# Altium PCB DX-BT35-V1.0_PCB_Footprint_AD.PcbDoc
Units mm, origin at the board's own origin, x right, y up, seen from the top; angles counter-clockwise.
Board outline 152.4 x 101.6 mm, 2 copper layers (Top Layer, Bottom Layer); 1 components, 0 nets, 26 pads, 0 vias.
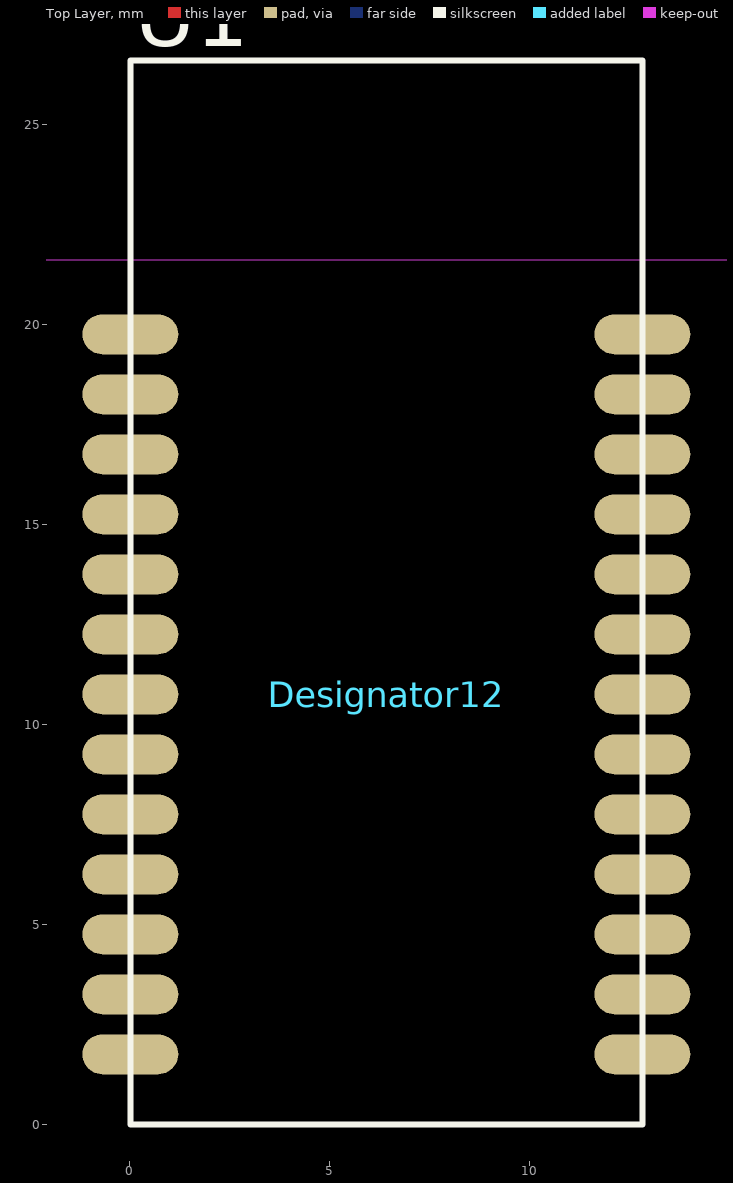
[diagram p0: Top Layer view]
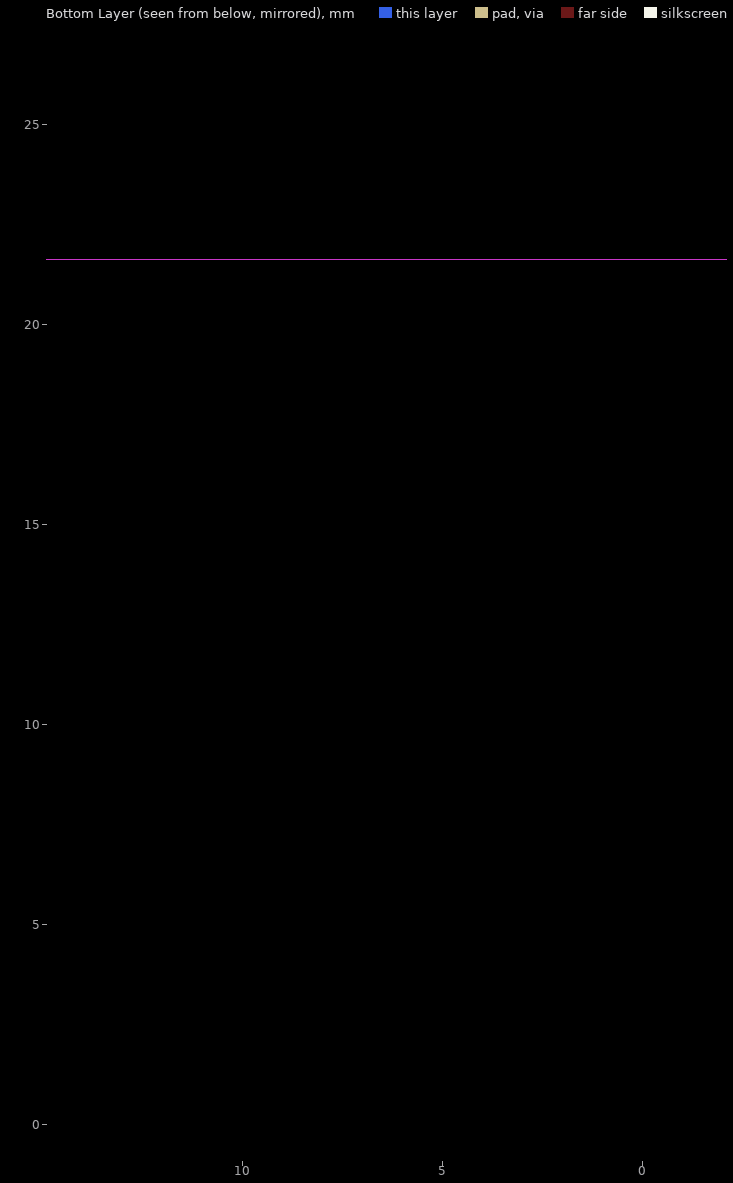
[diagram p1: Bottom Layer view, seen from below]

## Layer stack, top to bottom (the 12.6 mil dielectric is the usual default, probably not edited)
Top Solder: solder mask 0.0102, Solder Resist, Dk 3.5
Top Layer: signal copper 0.0356
Dielectric 1: dielectric 0.32, FR-4, Dk 4.8
Bottom Layer: signal copper 0.0356
Bottom Solder: solder mask 0.0102, Solder Resist, Dk 3.5

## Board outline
21.844,-336.55 174.244,-336.55 174.244,-234.95 21.844,-234.95

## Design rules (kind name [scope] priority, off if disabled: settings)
Clearance [All] p1: gap=0.254 ignorepadtopadclearanceinfootprint=FALSE except(0: Arc-Hole Track-Hole SMDPad-Hole THPad-Hole Via-Hole Fill-Hole Poly-Hole Region-Hole Text-Hole)
PolygonConnect [All] p1: connectstyle=Relief reliefconductorwidth=0.254 reliefentries=4 polygonreliefangle="90 Angle" airgapwidth=0.254
RoutingVias [All] p1: holewidth=0.711 width=1.27 viastyle="Through Hole" minholewidth=0.711 minwidth=1.27 maxholewidth=0.711 maxwidth=1.27
SolderMaskExpansion [All] p1: expansion=0.102 istentingtop=FALSE
Width [All] p1: maxlimit=0.254 minlimit=0.254 preferedwidth=0.254
30 further rules are at their usual default settings.

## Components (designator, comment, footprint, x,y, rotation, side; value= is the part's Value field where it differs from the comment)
Designator12 "Comment" PCBComponent_1 0.01,0 r0 top

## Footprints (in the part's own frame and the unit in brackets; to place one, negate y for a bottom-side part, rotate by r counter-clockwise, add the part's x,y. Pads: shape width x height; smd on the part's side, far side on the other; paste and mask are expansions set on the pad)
PCBComponent_1 [mm]
  oval 2.4x1 / inner oval 2.4x1 / far side round 0 all layers, no hole: 1(-0.002,19.749)
  oval 2.4x1 / inner round 0 / far side round 0 all layers, no hole: 2(-0.002,18.249) 3(-0.002,16.749) 4(-0.002,15.249) 5(-0.002,13.749) 6(-0.002,12.249) 7(-0.002,10.749) 8(-0.002,9.249) 9(-0.002,7.749) 10(-0.002,6.249) 11(-0.002,4.749)
  oval 2.4x1 / inner oval 0x0.9 / far side oval 0x1 all layers, no hole: 12(-0.002,3.249) 13(-0.002,1.749) 14(12.798,1.749) 15(12.798,3.249) 16(12.798,4.749) 17(12.798,6.249) 18(12.798,7.749) 19(12.798,9.249) 20(12.798,10.749) 21(12.798,12.249) 22(12.798,13.749) 23(12.798,15.249) 24(12.798,16.749) 25(12.798,18.249) 26(12.798,19.749)
  Keep-Out Layer region: -5,31.6 -5,21.61 17.805,21.61 17.805,31.6
  silkscreen extent 0,0 12.8,26.6

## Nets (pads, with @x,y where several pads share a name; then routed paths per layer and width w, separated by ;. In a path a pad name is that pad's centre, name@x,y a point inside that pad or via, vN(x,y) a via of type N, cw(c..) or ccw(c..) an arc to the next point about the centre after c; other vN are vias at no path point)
pads on no net: Designator12.1 Designator12.2 Designator12.3 Designator12.4 Designator12.5 Designator12.6 Designator12.7 Designator12.8 Designator12.9 Designator12.10 Designator12.11 Designator12.12 Designator12.13 Designator12.14 Designator12.15 Designator12.16 Designator12.17 Designator12.18 Designator12.19 Designator12.20 Designator12.21 Designator12.22 Designator12.23 Designator12.24 Designator12.25 Designator12.26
